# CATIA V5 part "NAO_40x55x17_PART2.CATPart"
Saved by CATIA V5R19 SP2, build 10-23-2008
Part number: NAO_40x55x17_PART2
Bounding box of the stored display mesh (mm): x 0 to 17, y -27.464 to 27.464, z -27.464 to 27.464
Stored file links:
  G:\EU_thinkMotion\CFAO_2010\MMS_groupe2\MMS_groupe2\OK\nrosalie\nrosalie_cfao_support_d_arme_legere_final\NAO_40x55x17_PART2.CATPart
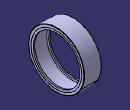
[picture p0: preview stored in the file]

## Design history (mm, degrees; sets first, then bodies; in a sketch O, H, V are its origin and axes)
Set1
  Point1: (0, 0, 0)
  Point2: (1, 0, 0)
  Point3: (0, 1, 0)
  Plane1: type 3Points, Element1 Point1, Element2 Point2, Element3 Point3
  Point4: (0, 0, 0)
  Point5: (1, 0, 0)
  Point6: (0, 1, 0)
  Plane2: type 3Points, Element1 Point4, Element2 Point5, Element3 Point6
  Point7: (0, 0, 0)
  Point8: (1, 0, 0)
  Point9: (0, 1, 0)
  Plane3: type 3Points, Element1 Point7, Element2 Point8, Element3 Point9
Body1 (main body)
  Sketch1 on Plane1, origin (0, 0, 0), H (1, 0, 0), V (0, 1, 0)
    point P1 (0, 25)
    point P2 (17, 25)
    line L1 (0, 25) -> (17, 25)
    point P3 (17, 25)
    point P4 (17, 27.2)
    line L2 (17, 25) -> (17, 27.2)
    arc A1 centre (16.7, 27.2) radius 0.3 from (17, 27.2) to (16.7, 27.5) ccw
    point P5 (16.7, 27.5)
    point P6 (0.3, 27.5)
    line L3 (16.7, 27.5) -> (0.3, 27.5)
    arc A2 centre (0.3, 27.2) radius 0.3 from (0.3, 27.5) to (0, 27.2) ccw
    point P7 (0, 27.2)
    point P8 (0, 25)
    line L4 (0, 27.2) -> (0, 25)
    point P9 (17, 0)
    point P10 (0, 0)
    axis line L5 (17, 0) -> (0, 0)
    point P11 (0, 25)
    point P12 (17, 25)
    point P13 (17, 25)
    point P14 (17, 27.2)
    point P15 (17, 27.2)
    point P16 (16.7, 27.5)
    point P17 (16.7, 27.5)
    point P18 (0.3, 27.5)
    point P19 (0.3, 27.5)
    point P20 (0, 27.2)
    point P21 (0, 27.2)
    point P22 (0, 25)
    coincidence: P11 P22, P12 P13, P14 P15, P16 P17, P18 P19, P20 P21
  Shaft1: profile Sketch1, axis Sketch1.L5, angle 360
  Sketch2 on Plane2, origin (0, 0, 0), H (1, 0, 0), V (0, 1, 0)
    point P1 (0.16, 25)
    point P2 (0.16, 23)
    line L1 (0.16, 25) -> (0.16, 23)
    point P3 (0.16, 23)
    point P4 (1.6, 23)
    line L2 (0.16, 23) -> (1.6, 23)
    point P5 (1.6, 23)
    point P6 (1.6, 25)
    line L3 (1.6, 23) -> (1.6, 25)
    point P7 (1.6, 25)
    point P8 (0.16, 25)
    line L4 (1.6, 25) -> (0.16, 25)
    point P9 (50, 0)
    point P10 (-50, 0)
    axis line L5 (50, 0) -> (-50, 0)
    point P11 (0.16, 25)
    point P12 (0.16, 23)
    point P13 (0.16, 23)
    point P14 (1.6, 23)
    point P15 (1.6, 23)
    point P16 (1.6, 25)
    point P17 (1.6, 25)
    point P18 (0.16, 25)
    coincidence: P11 P18, P12 P13, P14 P15, P16 P17
  Shaft2: profile Sketch2, axis Sketch2.L5, angle 0, second angle 360
  Sketch3 on Plane3, origin (0, 0, 0), H (1, 0, 0), V (0, 1, 0)
    point P1 (15.4, 25)
    point P2 (15.4, 23)
    line L1 (15.4, 25) -> (15.4, 23)
    point P3 (15.4, 23)
    point P4 (16.84, 23)
    line L2 (15.4, 23) -> (16.84, 23)
    point P5 (16.84, 23)
    point P6 (16.84, 25)
    line L3 (16.84, 23) -> (16.84, 25)
    point P7 (16.84, 25)
    point P8 (15.4, 25)
    line L4 (16.84, 25) -> (15.4, 25)
    point P9 (50, 0)
    point P10 (-50, 0)
    axis line L5 (50, 0) -> (-50, 0)
    point P11 (15.4, 25)
    point P12 (15.4, 23)
    point P13 (15.4, 23)
    point P14 (16.84, 23)
    point P15 (16.84, 23)
    point P16 (16.84, 25)
    point P17 (16.84, 25)
    point P18 (15.4, 25)
    coincidence: P11 P18, P12 P13, P14 P15, P16 P17
  Shaft3: profile Sketch3, axis Sketch3.L5, angle 0, second angle 360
